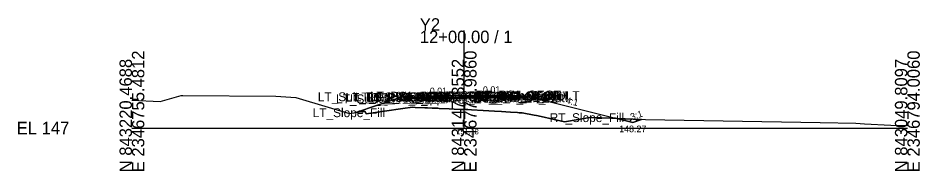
# Model space of a CAD drawing. Extents: x -26 to 2346977, y -10 to 843253.
# Drawn here: x -25.7 to 177.8, y 1490.3 to 1524.8 of the extents above; entities that cross this region are included whole.
import ezdxf

# ---------------------------------------------------------------- set-up
doc = ezdxf.new("R2010")
doc.units = 0
for name, color, linetype in [('Default', 7, 'Continuous'), ('Exist Cross Section Cell', 7, 'Continuous'), ('Exist XS Center Line Elevation Label', 7, 'Continuous'), ('Exist XS Ground Line', 7, 'Continuous'), ('Prop CMT Pvmt Course 1', 7, 'Continuous'), ('Prop CMT Pvmt Course 2', 7, 'Continuous'), ('Prop CMT Pvmt Course 3', 7, 'Continuous'), ('Prop CMT Pvmt Surface', 7, 'Continuous'), ('Prop CMT Pvmt Surface Shoulder', 7, 'Continuous'), ('Prop CMT Shld Paved Course 1', 7, 'Continuous'), ('Prop CMT Shld Paved Course 2', 7, 'Continuous'), ('Prop CMT Shld Paved Course 3', 7, 'Continuous'), ('Prop CMT Slope Grass', 7, 'Continuous'), ('Prop CMT Subgrade Earthwork', 7, 'Continuous'), ('Prop Road Sect_ Recs - UUC (Outline)', 7, 'Continuous'), ('Prop Road Sect_ Recs - UUC (pattern)', 7, 'Continuous'), ('Prop XS Earthwork Shape', 7, 'Continuous'), ('Prop XS SE Text', 7, 'Continuous'), ('Prop XS Side Slope Text', 7, 'Continuous'), ('Scratch_Level_2', 7, 'Continuous')]:
    doc.layers.add(name, color=color, linetype=linetype)

msp = doc.modelspace()

# ---------------------------------------------------------------- linework, layer by layer
at = {"layer": 'Exist Cross Section Cell'}
for p, q in [((74.95, 1500), (74.95, 1521.97)), ((0, 1500), (74.95, 1500)), ((74.95, 1500), (174.95, 1500))]:
    msp.add_line(p, q, dxfattribs=at)
at = {"layer": 'Exist XS Ground Line'}
msp.add_lwpolyline([(0, 1506.28), (6.38, 1505.99), (11.08, 1507.32), (11.5, 1507.32), (32.48, 1507.22), (36.98, 1506.91), (44.25, 1504.7), (49.1, 1503.29), (52.09, 1503.71), (52.64, 1503.7), (52.86, 1503.17), (61.14, 1504.39), (63.28, 1504.67), (63.88, 1504.66), (66.06, 1504.57), (66.68, 1504.55), (67.77, 1504.5), (68.99, 1504.45), (69.34, 1504.43), (71.55, 1504.33), (72.68, 1504.28), (74.13, 1504.21), (75.24, 1504.16), (75.77, 1504.14), (76.64, 1504.09), (79.26, 1503.96), (81.79, 1503.83), (83.36, 1503.74), (84.34, 1503.68), (85.45, 1503.61), (86.98, 1503.49), (87.39, 1503.44), (88.01, 1503.42), (90.73, 1502.89), (91.28, 1502.79), (92.31, 1502.56), (97.63, 1501.39), (100.65, 1501.89), (103.33, 1502.35), (108.18, 1502.21), (115.9, 1501.89), (155.28, 1501.24), (163.29, 1501.08), (165.29, 1500.96), (171.24, 1500.66), (174.95, 1500.57)], dxfattribs=at)
at = {"layer": 'Prop CMT Pvmt Course 1'}
for p, q in [((74.95, 1507.31), (62.95, 1507.17)), ((62.95, 1507.17), (62.95, 1506.92)), ((62.95, 1506.92), (74.95, 1507.06)), ((74.95, 1507.31), (86.95, 1507.44)), ((74.95, 1507.06), (74.95, 1507.31)), ((74.95, 1507.06), (74.95, 1507.31)), ((86.95, 1507.19), (74.95, 1507.06)), ((74.95, 1507.06), (74.95, 1507.18)), ((74.95, 1507.18), (74.95, 1507.18)), ((74.95, 1507.18), (74.95, 1507.06)), ((74.95, 1507.06), (74.95, 1507.18)), ((74.95, 1507.18), (74.95, 1507.18)), ((74.95, 1507.18), (74.95, 1507.06)), ((74.95, 1507.06), (74.95, 1507.06)), ((74.95, 1507.06), (74.95, 1507.06)), ((86.95, 1507.44), (86.95, 1507.19))]:
    msp.add_line(p, q, dxfattribs=at)
at = {"layer": 'Prop CMT Pvmt Course 2'}
for p, q in [((62.95, 1506.92), (74.95, 1507.06)), ((74.95, 1507.06), (62.95, 1506.92)), ((62.95, 1506.92), (62.95, 1506.92)), ((86.95, 1507.19), (74.95, 1507.06)), ((74.95, 1507.06), (86.95, 1507.19)), ((74.95, 1507.06), (74.95, 1507.06)), ((74.95, 1507.06), (74.95, 1507.06)), ((86.95, 1507.19), (86.95, 1507.19))]:
    msp.add_line(p, q, dxfattribs=at)
at = {"layer": 'Prop CMT Pvmt Course 3'}
for p, q in [((74.95, 1507.06), (62.95, 1506.92)), ((62.95, 1506.92), (62.95, 1506.59)), ((62.95, 1506.59), (74.95, 1506.72)), ((74.95, 1507.06), (86.95, 1507.19)), ((74.95, 1506.72), (74.95, 1507.06)), ((74.95, 1506.72), (74.95, 1507.06)), ((86.95, 1506.85), (74.95, 1506.72)), ((86.95, 1507.19), (86.95, 1506.85))]:
    msp.add_line(p, q, dxfattribs=at)
at = {"layer": 'Prop CMT Pvmt Surface'}
for q in [(62.95, 1507.17), (86.95, 1507.44)]:
    msp.add_line((74.95, 1507.31), q, dxfattribs=at)
at = {"layer": 'Prop CMT Pvmt Surface Shoulder'}
for p, q in [((62.95, 1507.17), (62.95, 1507.17)), ((86.95, 1507.44), (86.95, 1507.44))]:
    msp.add_line(p, q, dxfattribs=at)
at = {"layer": 'Prop CMT Shld Paved Course 1'}
for p, q in [((62.95, 1507.17), (62.7, 1506.92)), ((62.7, 1506.92), (62.95, 1506.92)), ((62.95, 1507.17), (62.95, 1507.17)), ((62.95, 1506.92), (62.95, 1507.17)), ((86.95, 1507.44), (86.95, 1507.44)), ((86.95, 1507.44), (87.21, 1507.18)), ((86.95, 1507.19), (86.95, 1507.44)), ((87.21, 1507.18), (86.95, 1507.19))]:
    msp.add_line(p, q, dxfattribs=at)
at = {"layer": 'Prop CMT Shld Paved Course 2'}
for p, q in [((62.95, 1506.92), (62.7, 1506.92)), ((62.7, 1506.92), (62.7, 1506.92)), ((62.7, 1506.92), (62.95, 1506.92)), ((62.95, 1506.92), (62.95, 1506.92)), ((86.95, 1507.19), (87.21, 1507.18)), ((87.21, 1507.18), (86.95, 1507.19)), ((86.95, 1507.19), (86.95, 1507.19)), ((87.21, 1507.18), (87.21, 1507.18))]:
    msp.add_line(p, q, dxfattribs=at)
at = {"layer": 'Prop CMT Shld Paved Course 3'}
for p, q in [((62.2, 1506.91), (61.86, 1506.57)), ((61.86, 1506.57), (62.95, 1506.59)), ((62.7, 1506.92), (62.2, 1506.91)), ((62.95, 1506.92), (62.7, 1506.92)), ((62.95, 1506.59), (62.95, 1506.92)), ((86.95, 1507.19), (87.21, 1507.18)), ((86.95, 1506.85), (86.95, 1507.19)), ((88.05, 1506.83), (86.95, 1506.85)), ((87.21, 1507.18), (87.71, 1507.17)), ((87.71, 1507.17), (88.05, 1506.83))]:
    msp.add_line(p, q, dxfattribs=at)
at = {"layer": 'Prop CMT Slope Grass'}
for p, q in [((60.95, 1507.01), (50.26, 1503.45)), ((62.95, 1507.17), (60.95, 1507.01)), ((86.95, 1507.44), (88.95, 1507.28)), ((88.95, 1507.28), (112.99, 1501.26)), ((112.99, 1501.26), (114.98, 1501.93))]:
    msp.add_line(p, q, dxfattribs=at)
at = {"layer": 'Prop CMT Subgrade Earthwork'}
for p, q in [((61.86, 1506.57), (61.38, 1507.05)), ((62.95, 1506.59), (61.86, 1506.57)), ((74.95, 1506.72), (62.95, 1506.59)), ((74.95, 1506.72), (86.95, 1506.85)), ((86.95, 1506.85), (88.05, 1506.83)), ((88.05, 1506.83), (88.53, 1507.31))]:
    msp.add_line(p, q, dxfattribs=at)
at = {"layer": 'Prop Road Sect_ Recs - UUC (Outline)'}
msp.add_lwpolyline([(109.42, 1502.16), (112.99, 1501.26), (114.99, 1501.93)], close=True, dxfattribs=at)
msp.add_lwpolyline([(109.42, 1502.16), (112.99, 1501.26), (114.99, 1501.93)], close=True, dxfattribs=at)
at = {"layer": 'Prop Road Sect_ Recs - UUC (pattern)'}
for p, q in [((109.97, 1502.02), (110.08, 1502.13)), ((109.97, 1502.02), (110.08, 1502.13)), ((111.1, 1501.74), (111.43, 1502.08)), ((111.1, 1501.74), (111.43, 1502.08)), ((112.23, 1501.46), (112.79, 1502.02)), ((112.23, 1501.46), (112.79, 1502.02)), ((113.68, 1501.49), (114.15, 1501.96)), ((113.68, 1501.49), (114.15, 1501.96))]:
    msp.add_line(p, q, dxfattribs=at)
at = {"layer": 'Prop XS Earthwork Shape'}
for points in [[(88.95, 1507.28), (109.42, 1502.16), (108.18, 1502.21), (103.33, 1502.35), (100.65, 1501.89), (97.63, 1501.39), (92.31, 1502.56), (91.28, 1502.79), (90.73, 1502.89), (88.01, 1503.42), (87.39, 1503.44), (86.98, 1503.49), (85.45, 1503.61), (84.34, 1503.68), (83.36, 1503.74), (81.79, 1503.83), (79.26, 1503.96), (76.64, 1504.09), (75.77, 1504.14), (75.24, 1504.16), (74.13, 1504.21), (72.68, 1504.28), (71.55, 1504.33), (69.34, 1504.43), (68.99, 1504.45), (67.77, 1504.5), (66.68, 1504.55), (66.06, 1504.57), (63.88, 1504.66), (63.28, 1504.67), (61.14, 1504.39), (52.86, 1503.17), (52.64, 1503.7), (52.09, 1503.71), (50.26, 1503.45), (60.95, 1507.01), (61.38, 1507.05), (61.86, 1506.57), (62.95, 1506.59), (74.95, 1506.72), (86.95, 1506.85), (88.05, 1506.83), (88.53, 1507.31)], [(109.42, 1502.16), (114.98, 1501.93), (112.99, 1501.26)]]:
    msp.add_lwpolyline(points, close=True, dxfattribs=at)

# ---------------------------------------------------------------- texts
at = {"layer": 'Default'}
msp.add_text('-', height=0.0001, dxfattribs=at).set_placement((0, 1500))
at = {"layer": 'Exist Cross Section Cell'}
for s, p in [('Y2', (64.95, 1521.97)), ('12+00.00 / 1', (64.95, 1519.17)), ('EL 147', (-26, 1498.6))]:
    msp.add_text(s, height=2.8, dxfattribs=at).set_placement(p)
for s, p in [('E 2346755.4812', (2.8, 1490)), ('E 2346771.9860', (77.75, 1490)), ('E 2346794.0060', (177.75, 1490)), ('N 843220.4688', (0, 1490)), ('N 843147.3552', (74.95, 1490)), ('N 843049.8097', (174.95, 1490))]:
    msp.add_text(s, height=2.8, rotation=90, dxfattribs=at).set_placement(p)
at = {"layer": 'Exist XS Center Line Elevation Label'}
msp.add_text('151.18', height=1.2, dxfattribs=at).set_placement((73.19, 1498.58))
at = {"layer": 'Prop XS SE Text'}
for s, rotation, p in [('0.01', 0.6213, (67.21, 1507.6)), ('0.01', 0.6213, (79.21, 1507.88)), ('4:1', 345.9638, (97.8, 1505.6)), ('3:1', 18.4349, (112.74, 1501.75)), ('148.27', 360, (109.93, 1499.05))]:
    msp.add_text(s, height=1.5, rotation=rotation, dxfattribs=at).set_placement(p)
at = {"layer": 'Prop XS Side Slope Text'}
msp.add_text('3:1', height=1.5, rotation=18.4332, dxfattribs=at).set_placement((55.78, 1505.53))
at = {"layer": 'Scratch_Level_2'}
for s, p in [('LT_Sub_Trench_Out_DLT', (41.95, 1506.05)), ('LT_PS3_Shelf_Out', (48.18, 1505.91)), ('LT_GS_OS_CTL', (50.32, 1506.01)), ('LT_PS3_OEOP', (52.93, 1505.92)), ('LT_PS2_OEOP', (52.93, 1505.92)), ('LT_PV3_OEOT', (53.13, 1505.92)), ('LT_PV2_OEOT', (53.13, 1505.92)), ('LT_PV1_OEOT', (53.69, 1506.17)), ('LT_PS1_OEOP', (53.76, 1506.17)), ('RT_PV2_OEEOP', (64.21, 1506.06)), ('RT_PV3_OEEOP', (64.21, 1506.06)), ('LT_PV2_OEEOP', (64.26, 1506.06)), ('LT_PV3_OEEOP', (64.26, 1506.06)), ('RT_PV1_OEEOP', (64.78, 1506.18)), ('LT_PV1_OEEOP', (64.83, 1506.18)), ('RT_PV2_IEEOP', (64.86, 1506.06)), ('LT_PV2_IEEOP', (64.91, 1506.06)), ('RT_PV1_IEEOP', (65.43, 1506.18)), ('LT_PV1_IEEOP', (65.47, 1506.18)), ('PV2_PGL', (68.86, 1506.06)), ('RT_Sub_Trench_Out_DLT', (69.05, 1506.31)), ('PV1_PGL', (69.43, 1506.31)), ('RT_Sub_Trench_Out', (72.21, 1505.83)), ('RT_PS3_Shelf_Out', (73.65, 1506.17)), ('RT_Sub_OEOT', (76.98, 1505.85)), ('RT_PV3_OEOT', (77.08, 1506.19)), ('RT_PV2_OEOT', (77.08, 1506.19)), ('RT_PS3_OEOP', (77.4, 1506.18)), ('RT_PS2_OEOP', (77.4, 1506.18)), ('RT_PV1_OEOT', (77.65, 1506.44)), ('RT_PS1_OEOP', (77.71, 1506.44)), ('RT_GS_OS_CTL', (78.28, 1506.28)), ('LT_Sub_Trench_Out', (46.06, 1505.57)), ('LT_Sub_OEOT', (53.03, 1505.59)), ('RT_Sub_OEEOP', (64.12, 1505.72)), ('LT_Sub_OEEOP', (64.17, 1505.72)), ('LT_Slope_Fill', (40.78, 1502.45)), ('RT_Slope_Fill', (94.25, 1501.34))]:
    msp.add_text(s, height=2, dxfattribs=at).set_placement(p)

doc.saveas('drawing.dxf')
